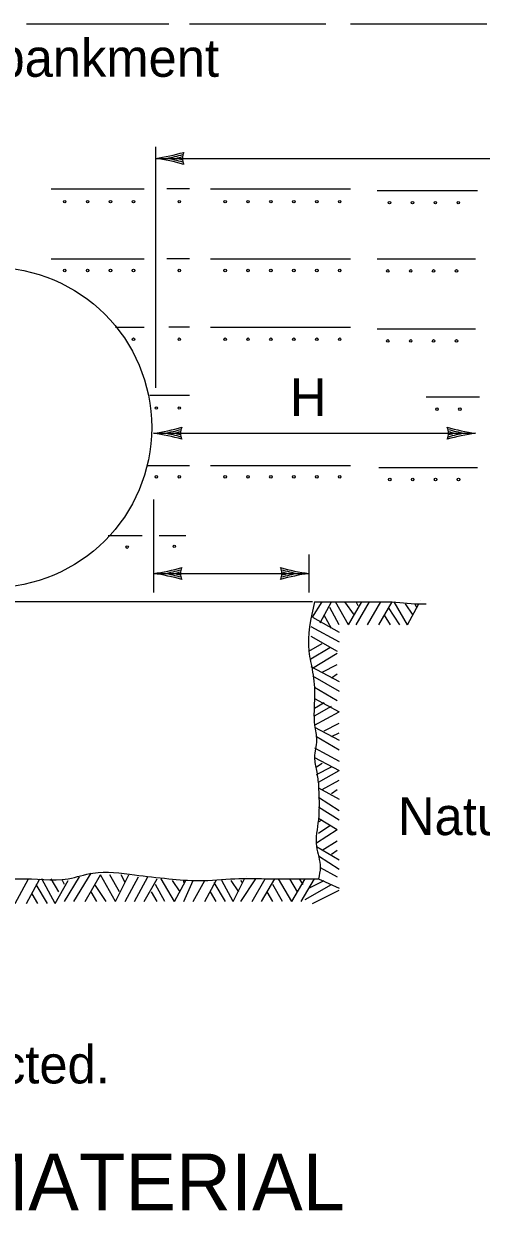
# Model space of a CAD drawing. Extents: x 0 to 390, y 0 to 265.
# Drawn here: x 216.9 to 241.1, y 109.5 to 172.1 of the extents above; entities that cross this region are included whole.
import ezdxf

# ---------------------------------------------------------------- set-up
doc = ezdxf.new("R2010")
doc.units = 0
doc.layers.add('D_Details', color=7, linetype='Continuous')

msp = doc.modelspace()

# ---------------------------------------------------------------- linework, layer by layer
at = {"layer": 'D_Details'}
for p, q in [((217.054, 172.101), (224.554, 172.101)), ((225.654, 172.101), (232.854, 172.101)), ((234.154, 172.101), (241.354, 172.101)), ((223.854, 165.601), (223.854, 152.901)), ((223.854, 165.001), (257.654, 165.001)), ((218.354, 163.401), (223.254, 163.401)), ((225.654, 163.401), (224.454, 163.401)), ((226.754, 163.401), (234.154, 163.401)), ((235.554, 163.301), (240.854, 163.301)), ((218.354, 159.701), (223.254, 159.701)), ((225.654, 159.701), (224.454, 159.701)), ((226.754, 159.701), (234.154, 159.701)), ((235.554, 159.701), (240.754, 159.701)), ((221.754, 156.101), (223.254, 156.101)), ((225.654, 156.101), (224.554, 156.101)), ((226.754, 156.101), (234.154, 156.101)), ((235.554, 156.001), (240.754, 156.001)), ((223.554, 152.501), (225.654, 152.501)), ((240.954, 152.401), (238.154, 152.401)), ((223.754, 150.501), (240.754, 150.501)), ((223.454, 148.801), (225.654, 148.801)), ((226.754, 148.801), (234.154, 148.801)), ((235.654, 148.701), (240.854, 148.701)), ((223.754, 147.001), (223.754, 142.101)), ((221.354, 145.101), (223.154, 145.101)), ((224.054, 145.101), (225.454, 145.101)), ((231.954, 144.101), (231.954, 142.101)), ((223.754, 143.101), (231.954, 143.101)), ((232.154, 141.601), (207.354, 141.601)), ((232.154, 140.801), (232.654, 141.601)), ((232.554, 140.501), (233.154, 141.601)), ((234.054, 140.401), (233.354, 141.601)), ((234.354, 140.901), (233.854, 141.601)), ((234.054, 140.401), (234.754, 141.601)), ((234.454, 140.401), (235.154, 141.601)), ((234.554, 141.401), (234.454, 141.601)), ((235.054, 140.401), (235.754, 141.601)), ((235.654, 140.401), (236.354, 141.601)), ((237.154, 140.401), (236.454, 141.601)), ((237.854, 141.701), (237.854, 141.701)), ((233.554, 140.401), (233.054, 141.301)), ((236.754, 140.401), (236.154, 141.301)), ((237.454, 140.901), (237.054, 141.501)), ((237.154, 140.401), (237.754, 141.501)), ((237.654, 141.301), (237.554, 141.501)), ((232.154, 140.801), (233.554, 140.001)), ((233.154, 140.201), (232.754, 140.901)), ((233.554, 140.601), (233.554, 140.601)), ((236.254, 140.401), (235.954, 140.901)), ((232.054, 140.301), (233.554, 139.501)), ((232.054, 139.801), (233.454, 139.001)), ((231.954, 139.001), (232.654, 139.401)), ((232.054, 138.601), (233.054, 139.201)), ((232.154, 138.101), (233.454, 138.901)), ((232.054, 138.201), (233.554, 137.401)), ((232.654, 137.901), (233.454, 138.301)), ((232.154, 137.701), (233.554, 136.901)), ((233.154, 137.601), (233.454, 137.801)), ((232.254, 137.101), (233.454, 136.401)), ((232.254, 136.501), (233.554, 135.801)), ((232.254, 136.001), (232.754, 136.301)), ((232.254, 135.601), (233.154, 136.101)), ((232.254, 135.101), (233.554, 135.801)), ((232.254, 135.001), (233.554, 134.301)), ((232.754, 134.801), (233.554, 135.201)), ((233.154, 134.501), (233.554, 134.701)), ((232.354, 134.501), (233.554, 133.801)), ((232.254, 133.901), (233.554, 133.201)), ((232.254, 133.401), (233.554, 132.701)), ((232.354, 132.901), (232.654, 133.101)), ((232.354, 132.501), (233.154, 132.901)), ((232.454, 132.101), (233.554, 132.701)), ((232.654, 131.701), (233.554, 132.201)), ((232.454, 131.801), (233.554, 131.201)), ((233.154, 131.501), (233.454, 131.701)), ((232.454, 131.301), (233.554, 130.601)), ((233.554, 131.201), (233.554, 131.201)), ((232.454, 130.801), (233.554, 130.101)), ((232.454, 130.201), (233.454, 129.601)), ((232.454, 130.001), (232.654, 130.101)), ((232.454, 129.401), (233.054, 129.801)), ((232.354, 128.901), (233.454, 129.601)), ((232.354, 128.701), (233.554, 128.001)), ((232.654, 128.501), (233.454, 129.001)), ((233.154, 128.301), (233.454, 128.501)), ((232.454, 128.201), (233.554, 127.501)), ((219.354, 127.201), (219.354, 127.201)), ((219.554, 125.801), (220.454, 127.301)), ((220.154, 125.801), (220.954, 127.201)), ((221.754, 125.801), (220.954, 127.201)), ((221.954, 126.301), (221.454, 127.201)), ((221.754, 125.801), (222.454, 127.201)), ((222.254, 126.801), (222.054, 127.201)), ((232.554, 127.601), (233.454, 127.101)), ((216.454, 125.701), (217.154, 127.001)), ((217.054, 125.701), (217.754, 127.001)), ((218.154, 125.701), (217.554, 126.701)), ((218.554, 125.701), (217.854, 127.001)), ((218.754, 126.301), (218.354, 127.001)), ((218.554, 125.701), (219.254, 126.901)), ((219.054, 126.701), (218.954, 126.901)), ((219.054, 125.801), (219.854, 127.101)), ((221.254, 125.801), (220.654, 126.701)), ((222.254, 125.801), (222.954, 127.101)), ((222.754, 125.801), (223.454, 127.101)), ((223.254, 125.801), (223.954, 127.001)), ((224.354, 125.801), (223.854, 126.701)), ((224.854, 125.801), (224.154, 127.001)), ((225.154, 126.301), (224.754, 126.901)), ((224.854, 125.801), (225.454, 126.901)), ((225.354, 125.801), (225.854, 126.901)), ((225.354, 126.801), (225.354, 126.901)), ((225.854, 125.801), (226.454, 126.901)), ((226.454, 125.801), (227.054, 126.901)), ((227.554, 125.801), (226.954, 126.801)), ((227.954, 125.801), (227.354, 126.901)), ((228.254, 126.301), (227.854, 126.901)), ((227.954, 125.801), (228.554, 127.001)), ((228.354, 125.801), (229.154, 127.001)), ((228.454, 126.801), (228.354, 126.901)), ((228.654, 127.101), (228.654, 127.101)), ((228.954, 125.801), (229.654, 127.001)), ((229.454, 125.801), (230.154, 127.001)), ((230.554, 125.801), (230.054, 126.701)), ((231.054, 125.801), (230.354, 127.001)), ((231.354, 126.301), (230.954, 127.001)), ((231.054, 125.801), (231.754, 127.001)), ((231.654, 126.701), (231.454, 127.001)), ((231.554, 125.801), (232.254, 127.001)), ((231.754, 125.901), (233.154, 126.701)), ((231.954, 126.501), (232.754, 126.901)), ((232.454, 127.001), (233.554, 126.501)), ((217.654, 125.701), (217.354, 126.201)), ((220.754, 125.801), (220.454, 126.301)), ((223.954, 125.801), (223.654, 126.301)), ((227.054, 125.801), (226.754, 126.301)), ((230.054, 125.801), (229.754, 126.301)), ((232.154, 125.701), (233.554, 126.401))]:
    msp.add_line(p, q, dxfattribs=at)
msp.add_lwpolyline([(232.254, 141.601), (233.154, 141.601), (234.454, 141.601), (235.154, 141.601), (236.354, 141.601), (237.554, 141.501), (238.154, 141.501)], dxfattribs=at)
for centre, radius in [((219.066, 162.714), 0.0674), ((220.276, 162.714), 0.0674), ((221.485, 162.714), 0.0674), ((222.695, 162.714), 0.0674), ((225.114, 162.714), 0.0674), ((227.533, 162.714), 0.0674), ((228.742, 162.714), 0.0674), ((229.952, 162.714), 0.0674), ((231.161, 162.714), 0.0674), ((232.371, 162.714), 0.0674), ((233.581, 162.714), 0.0674), ((236.213, 162.665), 0.0674), ((237.423, 162.665), 0.0674), ((238.632, 162.665), 0.0674), ((239.842, 162.665), 0.0674), ((215.21, 150.802), 8.447), ((219.066, 159.086), 0.0674), ((220.276, 159.086), 0.0674), ((221.485, 159.086), 0.0674), ((222.695, 159.086), 0.0674), ((225.114, 159.086), 0.0674), ((227.533, 159.086), 0.0674), ((228.742, 159.086), 0.0674), ((229.952, 159.086), 0.0674), ((231.161, 159.086), 0.0674), ((232.371, 159.086), 0.0674), ((233.581, 159.086), 0.0674), ((236.118, 159.062), 0.0674), ((237.328, 159.062), 0.0674), ((238.538, 159.062), 0.0674), ((239.747, 159.062), 0.0674), ((222.695, 155.457), 0.0674), ((225.114, 155.457), 0.0674), ((227.533, 155.457), 0.0674), ((228.742, 155.457), 0.0674), ((229.952, 155.457), 0.0674), ((231.161, 155.457), 0.0674), ((232.371, 155.457), 0.0674), ((233.581, 155.457), 0.0674), ((236.118, 155.369), 0.0674), ((237.328, 155.369), 0.0674), ((238.538, 155.369), 0.0674), ((239.747, 155.369), 0.0674), ((223.904, 151.829), 0.0674), ((225.114, 151.829), 0.0674), ((238.717, 151.772), 0.0674), ((239.927, 151.772), 0.0674), ((223.904, 148.2), 0.0674), ((225.114, 148.2), 0.0674), ((227.533, 148.2), 0.0674), ((228.742, 148.2), 0.0674), ((229.952, 148.2), 0.0674), ((231.161, 148.2), 0.0674), ((232.371, 148.2), 0.0674), ((233.581, 148.2), 0.0674), ((236.223, 148.057), 0.0674), ((237.433, 148.057), 0.0674), ((238.642, 148.057), 0.0674), ((239.852, 148.057), 0.0674), ((222.358, 144.496), 0.0674), ((224.852, 144.534), 0.0674)]:
    msp.add_circle(centre, radius, dxfattribs=at)
for centre, radius, start, end in [((222.288, 176.141), 11.25, 278, 285.81169), ((222.288, 153.86), 11.25, 74.18653, 82), ((222.288, 176.141), 11.35, 281.00099, 285.43008), ((222.288, 153.86), 11.35, 74.56992, 78.99901), ((222.288, 176.141), 11.45, 283.35937, 285.17092), ((222.288, 153.86), 11.45, 74.82908, 76.64064), ((225.978, 165.001), 0.699, 153.215, 206.78499), ((222.188, 161.641), 11.25, 278, 285.81169), ((222.188, 139.36), 11.25, 74.18653, 82), ((222.188, 161.641), 11.35, 281.00099, 285.43008), ((222.188, 139.36), 11.35, 74.56992, 78.99901), ((222.188, 161.641), 11.45, 283.35937, 285.17092), ((222.188, 139.36), 11.45, 74.82908, 76.64064), ((225.878, 150.501), 0.699, 153.215, 206.78499), ((242.319, 161.641), 11.25, 254.18653, 262), ((238.63, 150.501), 0.699, 333.215, 26.78499), ((242.319, 139.36), 11.25, 98, 105.81169), ((242.319, 161.641), 11.35, 254.56992, 258.99901), ((242.319, 139.36), 11.35, 101.00099, 105.43008), ((242.319, 161.641), 11.45, 254.82908, 256.64064), ((242.319, 139.36), 11.45, 103.35937, 105.17092), ((222.188, 154.241), 11.25, 278, 285.81169), ((222.188, 131.96), 11.25, 74.18653, 82), ((222.188, 154.241), 11.35, 281.00099, 285.43008), ((222.188, 131.96), 11.35, 74.56992, 78.99901), ((222.188, 154.241), 11.45, 283.35937, 285.17092), ((222.188, 131.96), 11.45, 74.82908, 76.64064), ((225.878, 143.101), 0.699, 153.215, 206.78499), ((233.519, 154.241), 11.25, 254.18653, 262), ((229.83, 143.101), 0.699, 333.215, 26.78499), ((233.519, 131.96), 11.25, 98, 105.81169), ((233.519, 154.241), 11.35, 254.56992, 258.99901), ((233.519, 131.96), 11.35, 101.00099, 105.43008), ((233.519, 154.241), 11.45, 254.82908, 256.64064), ((233.519, 131.96), 11.45, 103.35937, 105.17092)]:
    msp.add_arc(centre, radius, start, end, dxfattribs=at)
for points in [[(232.254, 141.601), (231.954, 139.001), (232.154, 137.901), (232.254, 136.601), (232.254, 135.101), (232.354, 134.301), (232.254, 133.401), (232.354, 132.701), (232.454, 132.001)], [(232.454, 132.001), (232.454, 130.101), (232.354, 128.701), (232.554, 127.601), (232.454, 127.001)], [(198.554, 126.901), (198.754, 126.901), (200.254, 127.101), (201.754, 127.001), (203.154, 127.001), (204.254, 126.801), (205.154, 127.001), (206.254, 127.201), (208.254, 127.101), (209.654, 127.001), (210.654, 127.101), (212.354, 127.001), (213.854, 127.001), (214.654, 127.101), (215.254, 127.001), (216.654, 127.001), (219.254, 127.001), (220.554, 127.301), (222.754, 127.201), (224.554, 127.001), (226.154, 126.901), (228.054, 127.001), (229.654, 127.001), (231.454, 127.001), (232.454, 127.001)]]:
    msp.add_spline(points, degree=3, dxfattribs=at)

# ---------------------------------------------------------------- texts
for s, height, p in [('Roadway embankment', 2, (199.857, 169.302)), ('H', 2, (230.957, 151.402)), ('Natural ground', 2, (236.657, 129.302)), ('foundation fill material properly compacted.', 2, (170.457, 116.202)), ('ON UNSTABLE MATERIAL', 3, (184.374, 109.502))]:
    msp.add_text(s, height=height, dxfattribs=at).set_placement(p)

doc.saveas('drawing.dxf')
